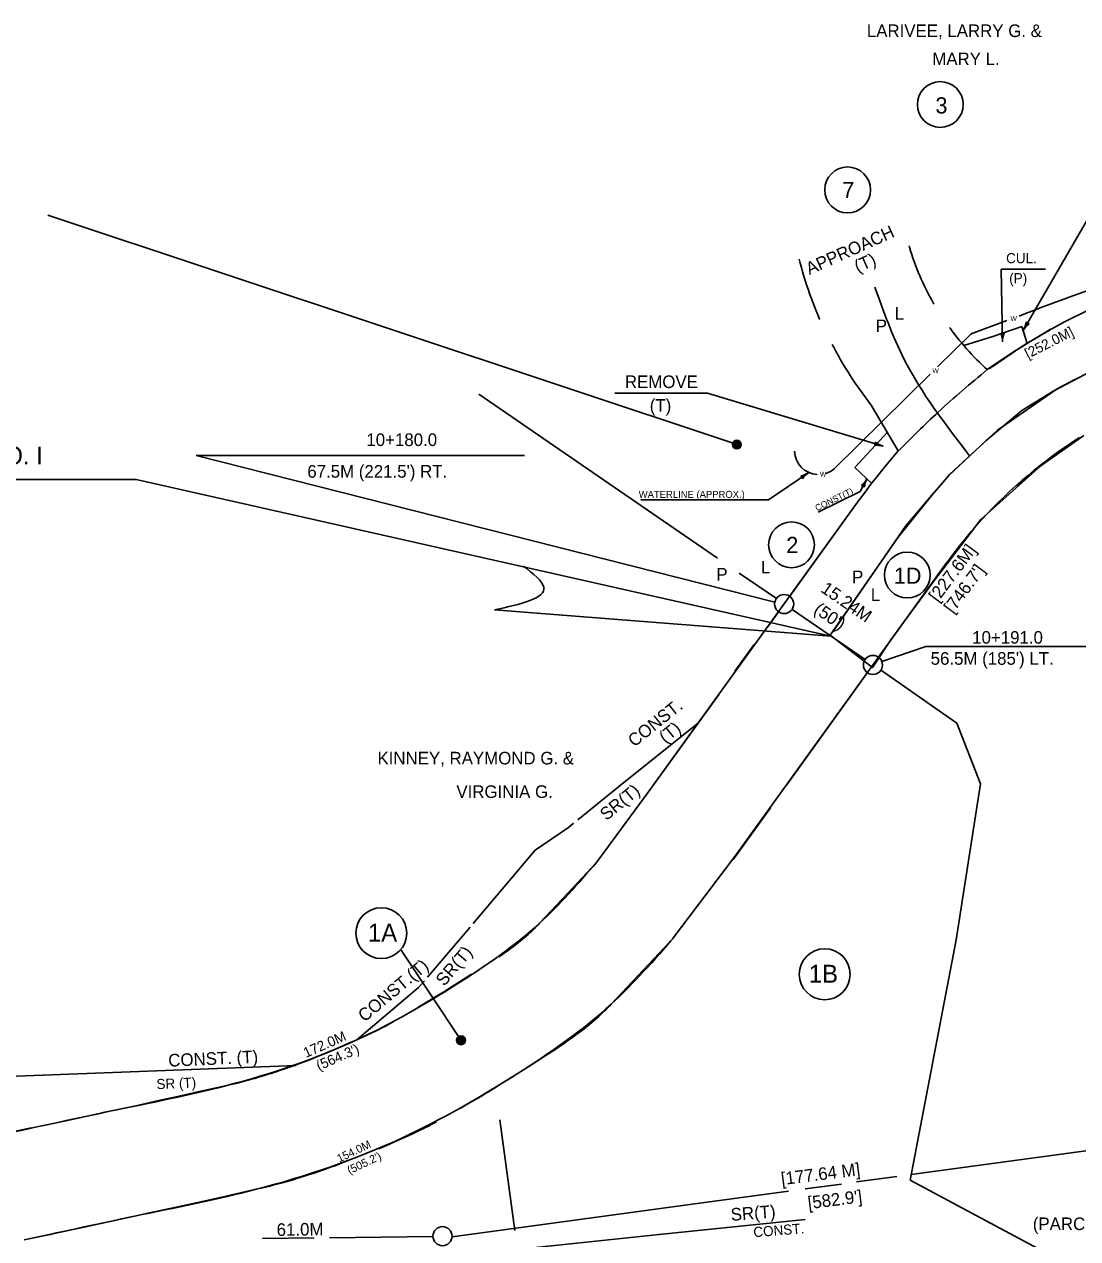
# Model space of a CAD drawing. Extents: x 624 to 1448, y 1599 to 1865.
# Drawn here: x 922.4 to 1071.5, y 1693.4 to 1865.2 of the extents above; entities that cross this region are included whole.
import ezdxf

# ---------------------------------------------------------------- set-up
doc = ezdxf.new("R2010")
doc.units = 0
for name, color, linetype in [('C_I', 7, 'Continuous'), ('C_TIC', 7, 'Continuous'), ('CPSM', 7, 'Continuous'), ('L_A', 7, 'Continuous'), ('L_C', 7, 'Continuous'), ('L_I', 7, 'Continuous'), ('Level 30', 7, 'Continuous'), ('ODIML_P', 7, 'Continuous')]:
    doc.layers.add(name, color=color, linetype=linetype)

msp = doc.modelspace()

# ---------------------------------------------------------------- linework, layer by layer
at = {"layer": 'C_I'}
for p, q in [((1073.8, 1839.17), (1063.81, 1821.9)), ((1060.66, 1830.57), (1066.97, 1830.57)), ((1060.66, 1830.57), (1060.88, 1820.29)), ((1056.41, 1821.4), (1061.49, 1823.29)), ((1064.23, 1823.09), (1064.38, 1822.89)), ((1064.26, 1822.94), (1064.24, 1822.73)), ((1064.49, 1822.81), (1064.32, 1822.68)), ((1064.63, 1822.86), (1064.38, 1822.89)), ((1056.41, 1821.4), (1051.69, 1816.74)), ((1060.62, 1821.52), (1060.85, 1821.43)), ((1060.72, 1821.41), (1060.81, 1821.21)), ((1061.08, 1821.53), (1060.85, 1821.43)), ((1060.98, 1821.41), (1060.91, 1821.22)), ((1050.63, 1815.7), (1037.06, 1802.34)), ((1006.01, 1813.01), (1019.11, 1813.01)), ((1043.98, 1805.52), (1019.11, 1813.01)), ((1042.73, 1805.65), (1042.89, 1805.85)), ((1042.86, 1806.09), (1042.89, 1805.84)), ((1042.87, 1805.71), (1043.08, 1805.74)), ((1042.94, 1805.97), (1043.1, 1805.83)), ((1027.74, 1797.92), (1033.47, 1801.81)), ((1032.32, 1801.31), (1032.52, 1801.17)), ((1032.46, 1801.29), (1032.67, 1801.33)), ((1032.57, 1800.93), (1032.52, 1801.17)), ((1032.61, 1801.08), (1032.73, 1801.25)), ((1040.72, 1799.11), (1041.68, 1800.92)), ((1034.8, 1796.19), (1040.72, 1799.11)), ((1040.9, 1799.93), (1041.15, 1799.91)), ((1041.04, 1799.99), (1041.2, 1800.12)), ((1041.31, 1799.72), (1041.15, 1799.91)), ((1041.27, 1799.87), (1041.29, 1800.08)), ((1009.67, 1797.92), (1027.74, 1797.92))]:
    msp.add_line(p, q, dxfattribs=at)
for centre, radius, start, end in [((1060.85, 1823.62), 3.42, 329.9416, 351.1649), ((1066.77, 1820.19), 3.42, 128.7446, 149.9678), ((1057.46, 1820.22), 3.42, 1.2123, 22.4355), ((1064.3, 1820.36), 3.42, 160.0152, 181.2385), ((1043.01, 1802.24), 3.42, 73.4662, 94.6895), ((1044.95, 1808.8), 3.42, 232.2692, 253.4924), ((1034.83, 1804.91), 3.4, 181.395, 266.4872), ((1034.83, 1804.91), 3.4, 287.9925, 310.977), ((1031.54, 1804.64), 3.42, 283.0006, 304.2239), ((1035.39, 1798.98), 3.42, 124.1977, 145.4209), ((1038.65, 1802.51), 3.42, 311.0001, 332.2233), ((1044.71, 1799.33), 3.42, 152.1971, 173.4204)]:
    msp.add_arc(centre, radius, start, end, dxfattribs=at)
msp.add_spline([(1063.22, 1823.93), (1073.58, 1827.78), (1089.86, 1832.7), (1092.73, 1833.55)], degree=3, dxfattribs=at)
at = {"layer": 'C_TIC'}
for p, q in [((1047.93, 1702.5), (1083.77, 1707.35)), ((1032.95, 1700.47), (1038.09, 1701.16)), ((1040.21, 1701.45), (1045.91, 1702.22)), ((1016.61, 1698.26), (1030.6, 1700.15)), ((982.95, 1693.7), (1016.61, 1698.26)), ((956.15, 1693.44), (963.42, 1693.53)), ((965.62, 1693.56), (980.24, 1693.75))]:
    msp.add_line(p, q, dxfattribs=at)
at = {"layer": 'CPSM'}
for p, q in [((873.74, 1800.82), (938.24, 1800.82)), ((1036.58, 1778.66), (938.24, 1800.82)), ((1036.58, 1778.66), (988.97, 1782.36))]:
    msp.add_line(p, q, dxfattribs=at)
msp.add_spline([(988.97, 1782.36), (995.95, 1785.58), (993.07, 1788.57)], degree=3, dxfattribs=at)
at = {"layer": 'L_A'}
msp.add_line((925.72, 1838.21), (1022.91, 1805.91), dxfattribs=at)
msp.add_lwpolyline([(1072.4, 1807.06), (1066.34, 1802.78), (1057.8, 1795.14), (1050.95, 1786.18), (1045.08, 1778.13), (1042.46, 1774.2), (1036.48, 1778.79), (1046.08, 1792.65), (1050.94, 1798.67), (1053.27, 1801.4), (1058.53, 1806.28), (1063.61, 1810.58), (1068.14, 1813.35), (1076.1, 1817.56)], dxfattribs=at)
for centre, radius in [((1023.27, 1805.75), 0.62), ((1023.27, 1805.74), 0.496), ((1023.27, 1805.74), 0.397), ((1023.27, 1805.73), 0.318), ((1023.27, 1805.73), 0.254), ((1023.27, 1805.72), 0.163)]:
    msp.add_circle(centre, radius, dxfattribs=at)
at = {"layer": 'L_C'}
for p, q in [((946.73, 1804.21), (1028.64, 1783.44)), ((946.73, 1804.21), (993.23, 1804.21)), ((1050.04, 1777.2), (1081.2, 1777.2)), ((975.74, 1734.25), (984.14, 1721.59))]:
    msp.add_line(p, q, dxfattribs=at)
for centre, radius in [((1052.06, 1853.86), 3.24), ((1038.94, 1841.78), 3.24), ((1031.01, 1791.58), 3.24), ((1047.39, 1787.3), 3.24), ((972.94, 1736.64), 3.6), ((1035.7, 1730.83), 3.6), ((984.22, 1721.49), 0.62), ((984.21, 1721.49), 0.496), ((984.21, 1721.5), 0.397), ((984.2, 1721.5), 0.318), ((984.2, 1721.5), 0.254), ((984.2, 1721.51), 0.163)]:
    msp.add_circle(centre, radius, dxfattribs=at)
at = {"layer": 'L_I'}
for p, q in [((1036.85, 1779.29), (1047.2, 1794.27)), ((1050.04, 1777.2), (1043.8, 1775.05)), ((1043.6, 1773.88), (1054.4, 1766.34)), ((1054.4, 1766.34), (1057.75, 1757.77)), ((1057.75, 1757.77), (1054.3, 1735.71)), ((1054.3, 1735.71), (1047.79, 1701.7)), ((989.74, 1710.25), (991.84, 1694.59)), ((1047.79, 1701.7), (1115.44, 1665.62))]:
    msp.add_line(p, q, dxfattribs=at)
for points in [[(1052.88, 1800.94), (1053.37, 1801.51), (1060.15, 1807.77), (1068.59, 1813.66), (1071.1, 1814.97)], [(986.73, 1812.89), (1020.52, 1789.69)], [(1047.2, 1794.27), (1051.12, 1798.87)], [(1023.59, 1787.58), (1028.86, 1783.97)], [(1031.08, 1782.44), (1041.42, 1775.34)]]:
    msp.add_lwpolyline(points, dxfattribs=at)
for centre in [(1029.97, 1783.2), (1042.53, 1774.58), (981.6, 1693.78)]:
    msp.add_circle(centre, 1.35, dxfattribs=at)
msp.add_spline([(1042.81, 1828.02), (1046.92, 1817.88), (1056.17, 1804.22)], degree=3, dxfattribs=at)
at = {"layer": 'Level 30'}
for p, q in [((1063.59, 1822.45), (1064.34, 1820.07)), ((1064, 1819.85), (1065.99, 1821.06)), ((1065.99, 1821.06), (1067.66, 1822.07)), ((1039.96, 1802.51), (1044.59, 1807.51)), ((1039.96, 1802.51), (1042.36, 1800.27)), ((991.67, 1691.85), (1012.27, 1694))]:
    msp.add_line(p, q, dxfattribs=at)
for points in [[(1055.38, 1819.78), (1059.51, 1821.02), (1063.59, 1822.45)], [(1058.98, 1816.45), (1061.36, 1818.09), (1063.48, 1819.52), (1065.01, 1820.47), (1067.62, 1822)], [(1000.75, 1752.68), (1007.28, 1757.97), (1017.84, 1766.41)], [(985.95, 1738.02), (994.74, 1748.36), (999.42, 1751.6), (1000.17, 1752.21)], [(979.49, 1730.43), (985.5, 1737.5)], [(969.52, 1721.59), (978.23, 1728.94), (979.05, 1729.91)], [(960.91, 1717.94), (887.94, 1715.13)], [(1012.27, 1694), (1032.92, 1696.14)]]:
    msp.add_lwpolyline(points, dxfattribs=at)
at = {"layer": 'ODIML_P'}
for p, q in [((1010.63, 1756.43), (1003.25, 1746.47)), ((1014.17, 1735.84), (1022.99, 1747.51))]:
    msp.add_line(p, q, dxfattribs=at)
for points in [[(1047.64, 1833.86), (1047.7, 1833.67), (1047.86, 1833.16), (1048.02, 1832.65), (1048.19, 1832.14), (1048.37, 1831.63), (1048.56, 1831.13), (1048.75, 1830.63), (1048.95, 1830.14), (1049.16, 1829.64), (1049.37, 1829.15), (1049.59, 1828.66), (1049.82, 1828.17), (1050.06, 1827.69), (1050.3, 1827.21), (1050.55, 1826.74), (1050.8, 1826.27), (1051.06, 1825.8), (1051.17, 1825.61)], [(1032.09, 1831.97), (1032.23, 1831.43), (1032.4, 1830.81), (1032.57, 1830.19), (1032.76, 1829.57), (1032.95, 1828.95), (1033.14, 1828.33), (1033.35, 1827.72), (1033.56, 1827.11), (1033.78, 1826.5), (1034.01, 1825.89), (1034.24, 1825.29), (1034.48, 1824.69), (1034.72, 1824.09), (1034.98, 1823.5), (1034.99, 1823.48)], [(1058.72, 1816.36), (1062.43, 1818.85), (1063.59, 1819.6), (1064.77, 1820.33), (1065.95, 1821.05), (1067.14, 1821.74), (1068.35, 1822.41), (1069.57, 1823.06), (1070.8, 1823.7), (1072.04, 1824.31), (1073.29, 1824.9), (1074.55, 1825.47), (1075.81, 1826.02), (1077.09, 1826.55), (1078.38, 1827.06), (1079.67, 1827.55), (1080.97, 1828.01), (1082.28, 1828.46), (1083.6, 1828.88), (1084.6, 1829.18)], [(1053.38, 1822.32), (1053.44, 1822.23), (1053.76, 1821.8), (1054.08, 1821.38), (1054.41, 1820.95), (1054.75, 1820.54), (1055.09, 1820.13), (1055.43, 1819.72), (1055.78, 1819.32), (1056.14, 1818.92), (1056.5, 1818.53), (1056.87, 1818.14), (1057.24, 1817.76), (1057.62, 1817.39), (1058, 1817.02), (1058.39, 1816.65), (1058.72, 1816.36), (1058.72, 1816.36), (1062.43, 1818.85), (1063.59, 1819.6), (1064.77, 1820.33), (1065.95, 1821.05), (1067.14, 1821.74), (1068.35, 1822.41), (1069.57, 1823.06), (1070.8, 1823.7), (1072.04, 1824.31)], [(1036.76, 1819.93), (1037.02, 1819.45), (1037.32, 1818.88), (1037.64, 1818.31), (1037.96, 1817.75), (1038.29, 1817.19), (1038.62, 1816.64), (1038.96, 1816.09), (1039.31, 1815.54), (1039.66, 1815), (1040.02, 1814.46), (1040.38, 1813.93), (1040.75, 1813.4), (1041.13, 1812.87), (1041.51, 1812.35), (1041.9, 1811.84), (1042.29, 1811.34), (1042.29, 1811.34), (1046.12, 1804.85), (1046.12, 1804.85), (1043.98, 1802.3), (1043.11, 1801.23), (1042.25, 1800.14), (1041.42, 1799.04), (1040.64, 1797.98), (1040.6, 1797.93), (1030.76, 1784.3)], [(1042.29, 1811.34), (1046.12, 1804.85)], [(1052.92, 1788.96), (1053.63, 1789.92), (1054.31, 1790.82), (1055.01, 1791.71), (1055.72, 1792.58), (1056.45, 1793.45), (1057.19, 1794.3), (1057.95, 1795.14), (1058.72, 1795.97), (1059.5, 1796.79), (1060.3, 1797.59), (1061.11, 1798.38), (1061.93, 1799.15), (1062.77, 1799.91), (1063.62, 1800.66), (1064.48, 1801.4), (1065.35, 1802.12), (1066.23, 1802.82), (1067.13, 1803.51), (1068.03, 1804.19), (1068.95, 1804.85), (1069.88, 1805.5), (1070.82, 1806.12), (1071.77, 1806.74)], [(1062.88, 1799.91), (1063.67, 1800.61), (1064.53, 1801.34), (1065.39, 1802.06), (1066.28, 1802.76), (1067.17, 1803.45), (1068.08, 1804.13), (1069, 1804.79), (1069.92, 1805.43), (1069.95, 1805.45)], [(1046.12, 1804.85), (1043.98, 1802.3), (1043.11, 1801.23), (1042.25, 1800.14), (1041.42, 1799.04), (1040.64, 1797.98)], [(1040.6, 1797.93), (1010.63, 1756.43)], [(1043.33, 1775.67), (1052.96, 1789.01), (1052.92, 1788.96), (1053.63, 1789.92), (1054.31, 1790.82), (1055.01, 1791.71), (1055.72, 1792.58), (1056.45, 1793.45), (1057.19, 1794.3), (1057.95, 1795.14), (1058.72, 1795.97), (1059.5, 1796.78)], [(1022.99, 1747.51), (1052.96, 1789.01)], [(1029.19, 1782.12), (1027.64, 1779.97)], [(1025.74, 1777.47), (1023, 1773.68)], [(1030.28, 1757.6), (1041.76, 1773.5)], [(1020.75, 1770.43), (1010.63, 1756.43), (1003.25, 1746.47), (1003.36, 1746.6), (999.35, 1742.32), (995.34, 1738.04), (995.18, 1737.88), (994.88, 1737.57), (994.58, 1737.27), (994.28, 1736.99), (994, 1736.72), (993.71, 1736.46), (993.44, 1736.21), (993.16, 1735.98), (992.9, 1735.75), (992.64, 1735.54), (992.38, 1735.33), (992.13, 1735.13), (991.89, 1734.94), (991.66, 1734.76), (991.19, 1734.41), (990.76, 1734.09), (990.34, 1733.8), (989.95, 1733.52), (989.6, 1733.28)], [(1022.75, 1747.06), (1023.05, 1747.46), (1028.02, 1754.35)], [(984.19, 1711.91), (984.49, 1712.07), (984.97, 1712.35), (985.43, 1712.62), (986.28, 1713.12), (987.02, 1713.56), (987.67, 1713.95), (988.24, 1714.29), (989.23, 1714.9), (989.97, 1715.36), (990.52, 1715.71), (991.35, 1716.23), (992.18, 1716.76), (993.06, 1717.33), (994.72, 1718.37), (995.44, 1718.83), (996.12, 1719.27), (996.75, 1719.67), (997.34, 1720.06), (997.89, 1720.42), (998.4, 1720.77), (998.88, 1721.09), (999.32, 1721.4), (999.74, 1721.7), (1000.13, 1721.97), (1000.49, 1722.24), (1000.82, 1722.49), (1001.13, 1722.72), (1001.42, 1722.94), (1001.69, 1723.15), (1001.95, 1723.36), (1002.18, 1723.54), (1002.4, 1723.72), (1002.81, 1724.06), (1003.16, 1724.36), (1003.46, 1724.63), (1003.73, 1724.87), (1003.96, 1725.08), (1004.16, 1725.26), (1004.5, 1725.59), (1004.75, 1725.84), (1004.94, 1726.03), (1005.23, 1726.32), (1005.5, 1726.61), (1009.99, 1731.39), (1014.48, 1736.16), (1014.17, 1735.84), (1019.9, 1743.42)], [(985.69, 1730.83), (983.87, 1729.67), (982.99, 1729.11), (982.17, 1728.59), (981.4, 1728.1), (980.67, 1727.66), (979.99, 1727.24), (979.35, 1726.86), (978.75, 1726.5), (978.18, 1726.16), (978.06, 1726.09)], [(974.63, 1724.09), (974.09, 1723.8), (973.52, 1723.51), (973.02, 1723.25), (972.58, 1723.03), (972.2, 1722.84), (971.52, 1722.51), (971.01, 1722.26), (970.62, 1722.08), (970.04, 1721.82), (969.46, 1721.55), (968.9, 1721.3), (968.36, 1721.06), (967.3, 1720.6), (966.31, 1720.18), (965.37, 1719.79), (964.5, 1719.43), (963.67, 1719.1), (962.9, 1718.79), (962.18, 1718.51), (961.49, 1718.25), (960.85, 1718.02), (960.25, 1717.8), (959.68, 1717.6), (959.15, 1717.41), (958.65, 1717.24), (958.19, 1717.09), (957.75, 1716.94), (957.33, 1716.81), (956.95, 1716.68), (956.22, 1716.46), (955.58, 1716.27), (955.02, 1716.1), (954.53, 1715.97), (954.1, 1715.85), (953.72, 1715.74), (953.06, 1715.57), (952.56, 1715.44), (952.18, 1715.35), (951.62, 1715.22), (951.06, 1715.09), (946.98, 1714.18), (943.92, 1713.5), (941.63, 1713), (938.18, 1712.24), (934.74, 1711.49), (927.88, 1710.01)], [(972.59, 1706.15), (973, 1706.32), (973.69, 1706.62), (974.73, 1707.08), (975.77, 1707.54), (976.31, 1707.78), (976.83, 1708.02), (977.34, 1708.25), (977.82, 1708.48), (978.29, 1708.71), (978.74, 1708.93), (979.18, 1709.15), (979.6, 1709.36), (980.01, 1709.57), (980.74, 1709.94)], [(923.36, 1709.11), (920.08, 1708.4), (914.5, 1707.67)], [(922.41, 1693.28), (923.31, 1693.43), (930.65, 1695.02), (937.99, 1696.6), (940.15, 1697.07), (943.92, 1697.9), (946.75, 1698.52), (951, 1699.46), (955.24, 1700.41), (955.9, 1700.56), (956.54, 1700.71), (957.16, 1700.87), (957.75, 1701.02), (958.33, 1701.17), (958.89, 1701.32), (959.43, 1701.47), (959.95, 1701.62), (960.45, 1701.77), (960.94, 1701.92), (961.41, 1702.06), (961.87, 1702.21), (962.31, 1702.35), (962.74, 1702.49), (963.56, 1702.76), (964.34, 1703.02), (965.06, 1703.28), (965.73, 1703.52), (966.37, 1703.75), (966.96, 1703.97), (967.51, 1704.18), (968.03, 1704.38), (968.28, 1704.47)]]:
    msp.add_lwpolyline(points, dxfattribs=at)
for points in [[(1046.13, 1804.85), (1051.77, 1810.35), (1058.71, 1816.36)], [(1003.36, 1746.6), (995.34, 1738.04), (983.91, 1729.6), (969.46, 1721.55), (951.06, 1715.09), (934.74, 1711.49), (920.09, 1708.33)], [(923.31, 1693.43), (937.99, 1696.6), (955.24, 1700.41), (975.74, 1707.61), (992.18, 1716.76), (1005.5, 1726.61), (1014.48, 1736.16)]]:
    msp.add_spline(points, degree=3, dxfattribs=at)

# ---------------------------------------------------------------- texts
at = {"layer": 'C_I'}
for s, height, rotation, p in [('APPROACH', 1.783, 24.1508, (1033.53, 1829.72)), ('(T)', 1.783, 24.1508, (1040.38, 1830.04)), ('[252.0M]', 1.426, 26.8049, (1064.47, 1817.88)), ('CONST(T)', 0.91, 26.1956, (1034.62, 1796.3)), ('[227.6M]', 1.783, 53.3496, (1051.71, 1783.36)), ("[746.7']", 1.783, 53.3496, (1053.85, 1781.75)), ('15.24M', 1.783, 325.5246, (1035.02, 1785.01)), ("(50')", 1.783, 325.5246, (1034.02, 1782.07)), ('CONST.', 1.783, 38.7324, (1008.75, 1762.89)), ('(T)', 1.783, 38.7324, (1013.14, 1763.41)), ('SR(T)', 1.783, 39.1532, (1004.8, 1752.48)), ('SR(T)', 1.783, 49.5586, (981.84, 1729.03)), ('CONST.(T)', 1.783, 40.0732, (970.58, 1723.99)), ('172.0M', 1.426, 23.6804, (962.29, 1718.99)), ('CONST. (T)', 1.783, 2.4302, (942.83, 1717.75)), ("(564.3')", 1.426, 23.6804, (964.11, 1717.17)), ('SR (T)', 1.426, 2.539, (941.15, 1714.57)), ('154.0M', 1.141, 25.4767, (967, 1704.18)), ("(505.2')", 1.141, 25.4767, (968.45, 1702.51)), ('[177.64 M]', 1.783, 7.1253, (1029.63, 1701)), ("[582.9']", 1.783, 7.1253, (1033.41, 1697.6)), ('SR(T)', 1.783, 4.4571, (1022.47, 1695.94)), ('61.0M', 1.783, 0.7439, (958.14, 1693.81)), ('CONST.', 1.426, 4.4571, (1025.66, 1693.63))]:
    msp.add_text(s, height=height, rotation=rotation, dxfattribs=at).set_placement(p)
for s, height, p in [('CUL.', 1.426, (1061.38, 1831.41)), ('(P)', 1.426, (1061.82, 1828.58)), ('W', 0.7, (1062, 1823.23)), ('W', 0.7, (1050.94, 1815.86)), ('REMOVE', 1.783, (1007.42, 1813.75)), ('(T)', 1.783, (1010.94, 1810.4)), ('W', 0.7, (1035.02, 1801.23)), ('WATERLINE (APPROX.)', 1, (1009.38, 1798.21))]:
    msp.add_text(s, height=height, dxfattribs=at).set_placement(p)
at = {"layer": 'CPSM'}
msp.add_text('BEGIN RELINQUISHMENT NO. I', height=2.54, dxfattribs=at).set_placement((874.28, 1802.94))
at = {"layer": 'L_A'}
for s, p in [('LARIVEE, LARRY G. &', (1041.67, 1863.4)), ('MARY L.', (1050.93, 1859.43)), ('KINNEY, RAYMOND G. &', (972.4, 1760.51)), ('VIRGINIA G.', (983.57, 1755.77)), ('(PARCEL #4)', (1065.16, 1694.64))]:
    msp.add_text(s, height=1.783, dxfattribs=at).set_placement(p)
at = {"layer": 'L_C'}
for s, height, p in [('3', 2.29, (1051.38, 1852.59)), ('7', 2.29, (1038.19, 1840.62)), ('10+180.0', 1.783, (970.83, 1805.55)), ("67.5M (221.5') RT.", 1.783, (962.47, 1801.07)), ('2', 2.29, (1030.26, 1790.41)), ('1D', 2.286, (1045.49, 1786.06)), ('10+191.0', 1.783, (1056.58, 1777.59)), ("56.5M (185') LT.", 1.783, (1050.7, 1774.61)), ('1A', 2.54, (971.04, 1735.44)), ('1B', 2.54, (1033.44, 1729.63))]:
    msp.add_text(s, height=height, dxfattribs=at).set_placement(p)
at = {"layer": 'L_I'}
for s, p in [('L', (1045.62, 1823.43)), ('P', (1042.93, 1821.66)), ('P', (1020.37, 1786.52)), ('L', (1026.68, 1787.52)), ('P', (1039.58, 1786.15)), ('L', (1042.23, 1783.62))]:
    msp.add_text(s, height=1.78, dxfattribs=at).set_placement(p)

doc.saveas('drawing.dxf')
